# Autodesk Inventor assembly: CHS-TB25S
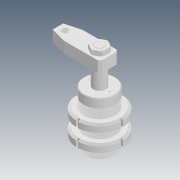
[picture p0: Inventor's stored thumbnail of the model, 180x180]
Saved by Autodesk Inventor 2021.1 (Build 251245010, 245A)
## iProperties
Created: 2019-04
Part Number: CHS-TB25S
Description: STEP AP203
Document SubType Name: Assembly
Designer: user
Title: chs-tb25s_asm.STEP
Revision Number: ÈÎºÎ
Sending System: SolidWorks 2017
Preprocessor: SwSTEP 2.0
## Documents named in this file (6)
- D:\Vault_2016\Projekty\Clamptek\Hydraulic\CHS\CHS-25\Inventor\CHS-TB25S\CHS-TB25S.iam
- D:\Vault_2016\Projekty\Clamptek\Hydraulic\CHS\CHS-25\Inventor\CHS-TB25S\CHS-TB25-03_1.ipt
- D:\Vault_2016\Projekty\Clamptek\Hydraulic\CHS\CHS-25\Inventor\CHS-TB25S\CHS-TB25-04_1.ipt
- D:\Vault_2016\Projekty\Clamptek\Hydraulic\CHS\CHS-25\Inventor\CHS-TB25S\CHS-25S-02_3_1.ipt
- D:\Vault_2016\Projekty\Clamptek\Hydraulic\CHS\CHS-25\Inventor\CHS-TB25S\CHS-25S-01_3.ipt
- D:\Vault_2016\Projekty\Clamptek\Hydraulic\CHS\CHS-25\Inventor\CHS-TB25S\M14_3.ipt
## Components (6 placed, 6 different names)
1. CHS-TB25-03_1_1
2. CHS-TB25-04_1_2
3. CHS-TB25-04_1_3
4. CHS-25S-02_3_1_4
5. CHS-25S-01_3_5
6. M14_3_6
